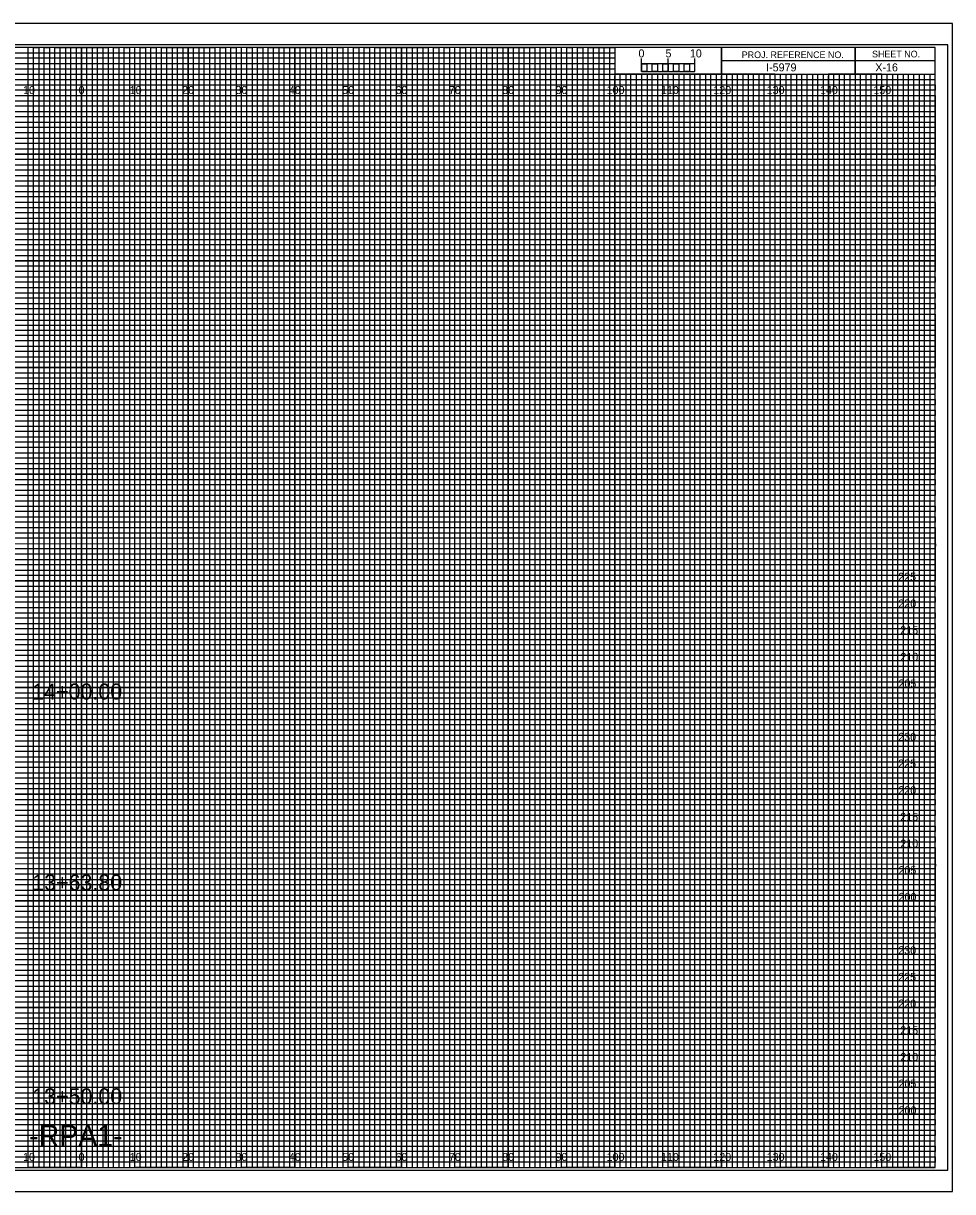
# Model space of a CAD drawing. Extents: x -13 to 323, y -5 to 654.
# Drawn here: x 149.1 to 323.3, y 435.5 to 654.5 of the extents above; entities that cross this region are included whole.
import ezdxf

# ---------------------------------------------------------------- set-up
doc = ezdxf.new("R2010")
doc.units = 0
for name, color, linetype in [('Prop XS Alignment Label', 7, 'Continuous'), ('Prop XS Bar Scale Labels', 7, 'Continuous'), ('Prop XS Elevation Labels', 7, 'Continuous'), ('Prop XS Offset Labels', 7, 'Continuous'), ('Prop XS Project Number', 7, 'Continuous'), ('Prop XS Sheet Number', 7, 'Continuous'), ('Prop XS Station Labels', 7, 'Continuous'), ('Sheet Cross Section CELL', 7, 'Continuous'), ('Sheet Cross Section Grid Major CELL', 7, 'Continuous'), ('Sheet Cross Section Grid Middle CELL', 7, 'Continuous'), ('Sheet Cross Section Grid Minor 1 CELL', 7, 'Continuous'), ('Sheet Cross Section Grid Minor 2 CELL', 7, 'Continuous'), ('Sheet Cross Section Scale CELL', 7, 'Continuous'), ('Sheet Cutting Line CELL', 7, 'Continuous'), ('Sheet DOT Grid CELL', 7, 'Continuous'), ('Sheet Plot Border Inside CELL', 7, 'Continuous'), ('Sheet Plot Border Outside CELL', 7, 'Continuous')]:
    doc.layers.add(name, color=color, linetype=linetype)

msp = doc.modelspace()

# ---------------------------------------------------------------- linework, layer by layer
at = {"layer": 'Sheet Cross Section CELL'}
for p, q in [((305, 650), (305, 645)), ((305, 645), (305, 650)), ((280, 647.5), (280, 645)), ((320, 647.49), (280, 647.49)), ((280, 645), (320, 645))]:
    msp.add_line(p, q, dxfattribs=at)
for points in [[(320, 650), (0, 650), (0, 440), (320, 440)], [(280, 650), (260, 650), (260, 645.03), (280, 645.03)], [(320, 650), (280, 650), (280, 645), (320, 645)]]:
    msp.add_lwpolyline(points, close=True, dxfattribs=at)
at = {"layer": 'Sheet Cross Section Grid Major CELL'}
for p, q in [((150, 650), (140, 650)), ((150, 440), (150, 650)), ((170, 650), (160, 650)), ((160, 650), (160, 440)), ((170, 440), (170, 650)), ((190, 650), (180, 650)), ((180, 650), (180, 440)), ((190, 440), (190, 650)), ((210, 650), (200, 650)), ((200, 650), (200, 440)), ((210, 440), (210, 650)), ((230, 650), (220, 650)), ((220, 650), (220, 440)), ((230, 440), (230, 650)), ((250, 650), (240, 650)), ((240, 650), (240, 440)), ((250, 440), (250, 650)), ((260, 650), (260, 440)), ((270, 440), (270, 645)), ((290, 645), (280, 645)), ((280, 645), (280, 440)), ((290, 440), (290, 645)), ((310, 645), (300, 645)), ((300, 645), (300, 440)), ((310, 440), (310, 645)), ((160, 440), (150, 440)), ((180, 440), (170, 440)), ((200, 440), (190, 440)), ((220, 440), (210, 440)), ((240, 440), (230, 440)), ((260, 440), (250, 440)), ((280, 440), (270, 440)), ((300, 440), (290, 440)), ((320, 440), (310, 440)), ((320, 440), (320, 440))]:
    msp.add_line(p, q, dxfattribs=at)
for points in [[(0, 640), (320, 640), (320, 630), (0, 630)], [(0, 620), (320, 620), (320, 610), (0, 610)], [(0, 600), (320, 600), (320, 590), (0, 590)], [(0, 580), (320, 580), (320, 570), (0, 570)], [(0, 560), (320, 560), (320, 550), (0, 550)], [(0, 540), (320, 540), (320, 530), (0, 530)], [(0, 520), (320, 520), (320, 510), (0, 510)], [(0, 500), (320, 500), (320, 490), (0, 490)], [(0, 480), (320, 480), (320, 470), (0, 470)], [(0, 460), (320, 460), (320, 450), (0, 450)]]:
    msp.add_lwpolyline(points, dxfattribs=at)
at = {"layer": 'Sheet Cross Section Grid Middle CELL'}
for points in [[(145, 440), (155, 440), (155, 650), (165, 650), (165, 440), (175, 440), (175, 650), (185, 650), (185, 440), (195, 440), (195, 650), (205, 650), (205, 440), (215, 440), (215, 650), (225, 650), (225, 440), (235, 440), (235, 650), (245, 650), (245, 440), (255, 440), (255, 650), (259.93, 650), (260, 650), (260, 645), (264.99, 645), (264.99, 440), (275, 440), (275, 645), (285, 645), (285, 440), (295, 440), (295, 645), (305, 645), (305, 440), (315, 440), (315, 645)], [(0, 645), (275, 645)], [(0, 625), (320, 625), (320, 635), (0, 635)], [(0, 605), (320, 605), (320, 615), (0, 615)], [(0, 585), (320, 585), (320, 595), (0, 595)], [(0, 565), (320, 565), (320, 575), (0, 575)], [(0, 545), (320, 545), (320, 555), (0, 555)], [(0, 525), (320, 525), (320, 535), (0, 535)], [(0, 505), (320, 505), (320, 515), (0, 515)], [(0, 485), (320, 485), (320, 495), (0, 495)], [(0, 465), (320, 465), (320, 475), (0, 475)], [(0, 445), (320, 445), (320, 455), (0, 455)]]:
    msp.add_lwpolyline(points, dxfattribs=at)
at = {"layer": 'Sheet Cross Section Grid Minor 1 CELL'}
for p, q in [((0, 649), (260, 649)), ((260, 649), (260, 647.98)), ((260, 647.98), (0, 647.98)), ((0, 647), (260, 647)), ((260, 647), (260, 645.89)), ((260, 645.89), (0, 645.89)), ((0, 644), (320, 644))]:
    msp.add_line(p, q, dxfattribs=at)
for points in [[(0, 643), (270, 643), (320, 643), (320, 642), (0, 642)], [(0, 641), (320, 641), (320, 639), (0, 639)], [(0, 638), (320, 638), (320, 637), (0, 636.98)], [(0, 636), (320, 636), (320, 634), (0, 634)], [(0, 633), (320, 633), (320, 632), (0, 632)], [(0, 631), (320, 631), (320, 629), (0, 629)], [(0, 628), (320, 628), (320, 627), (0, 627)], [(0, 626), (320, 626), (320, 624), (0, 624)], [(0, 623), (320, 623), (320, 622), (0, 622)], [(0, 621), (320, 621), (320, 619), (0, 619)], [(0, 618), (320, 618), (320, 617), (0, 617)], [(0, 616), (320, 616), (320, 613.95), (320, 613), (320, 612), (0, 612)], [(0, 614), (320, 614), (320, 613), (0, 613)], [(0, 611), (320, 611), (320, 609), (0, 609.03)], [(0, 609.03), (320, 609), (320, 608), (0, 608)], [(0, 607), (320, 607), (320, 606), (0, 606)], [(0, 604), (320, 604), (320, 603), (0, 603)], [(0, 602), (320, 602), (320, 601), (0, 601)], [(-0.07, 598.89), (320, 598.89), (320, 597.88), (-0.07, 597.88)], [(0, 597), (320, 597), (320, 596), (0, 596)], [(0, 594), (320, 594), (320, 593), (0, 593)], [(0, 592), (320, 592), (320, 591), (0, 591)], [(0, 589), (320, 589), (320, 588), (0, 588)], [(0, 587), (320, 587), (320, 586), (0, 586)], [(0, 584), (320, 584), (320, 583), (0, 583)], [(0, 582), (320, 582), (320, 581), (0, 581)], [(0, 579), (320, 579), (319.99, 577.98), (0, 578)], [(0, 577), (320, 577), (320, 576), (0, 576)], [(0, 574), (320, 574), (320, 573), (0, 573)], [(0, 572), (320, 572), (320, 571), (0, 571)], [(0, 569), (320, 569), (320, 568), (0, 568)], [(0, 567), (320, 567), (320, 566), (0, 566)], [(0, 564), (320, 564), (320, 563), (0, 563)], [(0, 562), (320, 562), (320, 561), (0, 561)], [(0, 559), (320, 559), (320, 558), (0, 558)], [(0, 556.99), (320.07, 556.91), (320, 556), (0, 556)], [(0, 554), (320, 554), (320, 553), (0, 553)], [(0, 552), (320, 552), (320, 551), (0, 551)], [(0, 549), (320, 549), (320, 548), (0, 548)], [(0, 547), (320, 547), (320, 546), (0, 546)], [(0, 544), (320, 544), (320, 543), (0, 543)], [(0, 542), (320, 542), (320, 541), (0, 541)], [(0, 539), (320, 539), (320, 538), (0, 538)], [(0, 537), (320, 537), (320, 536), (0, 536)], [(0, 534), (320, 534), (320, 533), (0, 533)], [(0, 532), (320, 532), (320, 531), (0, 531)], [(0, 529), (320, 529), (320, 528), (0, 528)], [(0, 527), (320, 527), (320, 526), (0, 526)], [(0, 524), (320, 524), (320, 523), (0, 523)], [(0, 522), (320, 522), (320, 521), (0, 521)], [(0, 519), (320, 519), (319.99, 517.98), (0, 518)], [(0, 517), (320, 517), (320, 516), (0, 516)], [(0, 514), (320, 514), (320, 513), (0, 513)], [(0, 512), (320, 512), (320, 511), (0, 511)], [(0, 509), (320, 509), (320, 508), (0, 508)], [(0, 507), (320, 507), (320, 506), (0, 506)], [(0, 504), (320, 504), (320, 503), (0, 503)], [(0, 502), (320, 502), (320, 501), (0, 501)], [(0, 499), (320, 499), (320, 498), (0, 498)], [(0, 496.99), (320.07, 496.91), (320, 496), (0, 496)], [(0, 494), (320, 494), (320, 493), (0, 493)], [(0, 492), (320, 492), (320, 491), (0, 491)], [(0, 489), (320, 489), (320, 488), (0, 488)], [(0, 487), (320, 487), (320, 486), (0, 486)], [(0, 484), (320, 484), (320, 483), (0, 483)], [(0, 482), (320, 482), (320, 481), (0, 481)], [(0, 479), (320, 479), (320, 478), (0, 478)], [(0, 477), (320, 477), (320, 476), (0, 476)], [(0, 474), (320, 474), (320, 473), (0, 473)], [(0, 472), (320, 472), (320, 471), (0, 471)], [(0, 469), (320, 469), (320, 468), (0, 468)], [(0, 467), (320, 467), (320, 466), (0, 466)], [(0, 464), (320, 464), (320, 463), (0, 463)], [(0, 462), (320, 462), (320, 461), (0, 461)], [(0, 459), (320, 459), (320, 458), (0, 458)], [(0, 457), (320, 457), (320, 456), (0, 456)], [(0, 454), (320, 454), (320, 453), (0, 453)], [(0, 452), (320, 452), (320, 451), (0, 451)], [(0, 449), (320, 449), (320, 448), (0, 448)], [(0, 447), (320, 447), (320, 446), (0, 446)], [(0, 444), (320, 444), (320, 443), (0, 443)], [(0, 442), (320, 442), (320, 441), (0, 441)]]:
    msp.add_lwpolyline(points, dxfattribs=at)
at = {"layer": 'Sheet Cross Section Grid Minor 2 CELL'}
for p, q in [((267, 645), (266.01, 645)), ((266.01, 645), (266.01, 440)), ((267, 440), (267, 645)), ((269, 645), (268, 645)), ((268, 645), (268, 440)), ((269, 440), (269, 645)), ((266.01, 440), (265, 440)), ((268, 440), (267, 440))]:
    msp.add_line(p, q, dxfattribs=at)
for points in [[(150, 440), (151, 440), (151, 650), (152, 650), (152, 440)], [(152, 440), (153, 440), (153, 650), (154, 650), (154, 440)], [(155, 440), (156, 440), (156, 650), (157, 650), (157, 440)], [(157, 440), (158, 440), (158, 650), (159, 650), (159, 440)], [(160, 440), (161, 440), (161, 650), (162, 650), (162, 440)], [(162, 440), (163, 440), (163, 650), (164, 650), (164, 440)], [(165, 440), (166, 440), (166, 650), (167, 650), (167, 440)], [(167, 440), (168, 440), (168, 650), (169, 650), (169, 440)], [(170, 440), (171, 440), (171, 650), (172, 650), (172, 440)], [(172, 440), (173, 440), (173, 650), (174, 650), (174, 440)], [(175, 440), (176, 440), (176, 650), (177, 650), (177, 440)], [(177, 440), (178, 440), (178, 650), (179, 650), (179, 440)], [(180, 440), (181, 440), (181, 650), (182, 650), (182, 440)], [(182, 440), (183, 440), (183, 650), (184, 650), (184, 440)], [(185, 440), (186, 440), (186, 650), (187, 650), (187, 440)], [(187, 440), (188, 440), (188, 650), (189, 650), (189, 440)], [(190, 440), (191, 440), (191, 650), (192, 650), (192, 440)], [(192, 440), (193, 440), (193, 650), (194, 650), (194, 440)], [(195, 440), (196, 440), (196, 650), (197, 650), (197, 440)], [(197, 440), (198, 440), (198, 650), (199, 650), (199, 440)], [(200, 440), (201, 440), (201, 650), (202, 650), (202, 440)], [(202, 440), (203, 440), (203, 650), (204, 650), (204, 440)], [(205, 440), (206, 440), (206, 650), (207, 650), (207, 440)], [(207, 440), (208, 440), (208, 650), (209, 650), (209, 440)], [(210, 440), (211, 440), (211, 650), (212, 650), (212, 440)], [(212, 440), (213, 440), (213, 650), (214, 650), (214, 440)], [(215, 440), (216, 440), (216, 650), (217, 650), (217, 440)], [(217, 440), (218, 440), (218, 650), (219, 650), (219, 440)], [(220, 440), (221, 440), (221, 650), (222, 650), (222, 440)], [(222, 440), (223, 440), (223, 650), (224, 650), (224, 440)], [(225, 440), (226, 440), (226, 650), (227, 650), (227, 440)], [(227, 440), (228, 440), (228, 650), (229, 650), (229, 440)], [(230, 440), (231, 440), (231, 650), (232, 650), (232, 440)], [(232, 440), (233, 440), (233, 650), (234, 650), (234, 440)], [(235, 440), (236, 440), (236, 650), (237, 650), (237, 440)], [(237, 440), (238, 440), (238, 650), (239, 650), (239, 440)], [(240, 440), (241, 440), (241, 650), (242, 650), (242, 440)], [(242, 440), (243, 440), (243, 650), (244, 650), (244, 440)], [(245, 440), (246, 440), (246, 650), (247, 650), (247, 440)], [(247, 440), (248, 440), (248, 650), (249, 650), (249, 440)], [(250, 440), (251, 440), (251, 650), (252, 650), (252, 440)], [(252, 440), (253, 440), (253, 650), (254, 650), (254, 440)], [(255, 440), (256, 440), (256, 650), (257, 650), (257, 440)], [(257, 440), (258, 440), (258, 650), (259, 650), (259, 440)], [(260, 440), (261, 440), (261, 645), (262.02, 645), (262.02, 440)], [(262, 440), (263, 440), (263, 645), (263.99, 645), (263.99, 440)], [(270, 440), (270.98, 440), (270.98, 645), (272, 645), (272, 440)], [(272, 440), (273, 440), (273, 645), (274.05, 645), (274.05, 440)], [(275, 440), (276, 440), (276, 645), (277, 645), (277, 440)], [(277, 440), (278, 440), (278, 645), (279, 645), (279, 440)], [(280, 440), (281, 440), (281, 645), (282, 645), (282, 440)], [(282, 440), (283, 440), (283, 645), (284, 645), (284, 440)], [(285, 440), (286, 440), (286, 645), (287, 645), (287, 440)], [(287, 440), (288, 440), (288, 645), (289, 645), (289, 440)], [(290, 440), (291, 440), (291, 645), (292, 645), (292, 440)], [(292, 440), (293, 440), (293, 645), (294, 645), (294, 440)], [(295, 440), (296, 440), (296, 645), (297, 645), (297, 440)], [(297, 440), (298, 440), (298, 645), (299, 645), (299, 440)], [(300, 440), (301, 440), (301, 645), (302, 645), (302, 440)], [(302, 440), (303, 440), (303, 645), (304, 645), (304, 440)], [(305, 440), (306, 440), (306, 645), (307, 645), (307, 440)], [(307, 440), (308, 440), (308, 645), (309, 645), (309, 440)], [(310, 440), (311, 440), (311, 645), (312, 645), (312, 440)], [(312, 440), (313, 440), (313, 645), (314, 645), (314, 440)], [(315, 440), (316, 440), (316, 645), (317, 645), (317, 440)], [(317, 440), (318, 440), (318, 645), (319, 645), (319, 440)]]:
    msp.add_lwpolyline(points, dxfattribs=at)
at = {"layer": 'Sheet Cross Section Scale CELL'}
for p, q in [((265, 645.49), (265, 647.9)), ((265, 646.9), (265, 647.9)), ((270, 645.49), (270, 647.9)), ((275, 645.49), (275, 647.9)), ((275, 646.9), (275, 647.9))]:
    msp.add_line(p, q, dxfattribs=at)
for points in [[(275, 646.9), (265, 646.9), (265, 645.49), (275, 645.49)], [(265, 646.9), (266, 646.9), (266, 645.49), (265, 645.49)], [(267, 646.9), (268, 646.9), (268, 645.49), (267, 645.49)], [(269, 646.9), (270, 646.9), (270, 645.49), (269, 645.49)], [(271, 646.9), (272, 646.9), (272, 645.49), (271, 645.49)], [(273, 646.9), (274, 646.9), (274, 645.49), (273, 645.49)]]:
    msp.add_lwpolyline(points, close=True, dxfattribs=at)
at = {"layer": 'Sheet Cutting Line CELL'}
for p, q in [((323.3, 654.5), (-13.4, 654.5)), ((-13.4, 435.5), (323.3, 435.5))]:
    msp.add_line(p, q, dxfattribs=at)
at = {"layer": 'Sheet DOT Grid CELL'}
for p, q in [((150, 440), (150, 650)), ((160, 440), (160, 650)), ((170, 440), (170, 650)), ((180, 440), (180, 650)), ((190, 440), (190, 650)), ((200, 440), (200, 650)), ((210, 440), (210, 650)), ((220, 440), (220, 650)), ((230, 440), (230, 650)), ((240, 440), (240, 650)), ((250, 440), (250, 650)), ((260, 440), (260, 644.69)), ((270, 440), (270, 644.69)), ((280, 440), (280, 644.69)), ((290, 440), (290, 644.69)), ((300, 440), (300, 644.69)), ((310, 440), (310, 644.69)), ((0, 640), (320, 640)), ((0, 630), (320, 630)), ((0, 620), (320, 620)), ((0, 610), (320, 610)), ((0, 600), (320, 600)), ((0, 590), (320, 590)), ((0, 580), (320, 580)), ((0, 570), (320, 570)), ((0, 560), (320, 560)), ((0, 550), (320, 550)), ((0, 540), (320, 540)), ((0, 530), (320, 530)), ((0, 520), (320, 520)), ((0, 510), (320, 510)), ((0, 500), (320, 500)), ((0, 490), (320, 490)), ((0, 480), (320, 480)), ((0, 470), (320, 470)), ((0, 460), (320, 460)), ((0, 450), (320, 450))]:
    msp.add_line(p, q, dxfattribs=at)
at = {"layer": 'Sheet Plot Border Inside CELL'}
msp.add_lwpolyline([(-10.8, 439.5), (322.4, 439.5), (322.4, 650.5), (-10.8, 650.5)], close=True, dxfattribs=at)
at = {"layer": 'Sheet Plot Border Outside CELL'}
msp.add_lwpolyline([(-13.4, 435.5), (323.3, 435.5), (323.3, 654.5), (-13.4, 654.5)], close=True, dxfattribs=at)

# ---------------------------------------------------------------- texts
at = {"layer": 'Prop XS Alignment Label'}
msp.add_text('-RPA1-', height=4, dxfattribs=at).set_placement((150.18, 444))
at = {"layer": 'Prop XS Bar Scale Labels'}
for s, p in [('5', (269.47, 648.12)), ('10', (274.04, 648.12))]:
    msp.add_text(s, height=1.5, dxfattribs=at).set_placement(p)
at = {"layer": 'Prop XS Elevation Labels'}
for s, p in [('225', (313.1, 550)), ('220', (313.12, 545)), ('215', (313.48, 540)), ('210', (313.5, 535)), ('205', (313.15, 530)), ('230', (313.11, 520)), ('225', (313.1, 515)), ('220', (313.12, 510)), ('215', (313.48, 505)), ('210', (313.5, 500)), ('205', (313.15, 495)), ('200', (313.17, 490)), ('230', (313.11, 480)), ('225', (313.1, 475)), ('220', (313.12, 470)), ('215', (313.48, 465)), ('210', (313.5, 460)), ('205', (313.15, 455)), ('200', (313.17, 450))]:
    msp.add_text(s, height=1.5, dxfattribs=at).set_placement(p)
at = {"layer": 'Prop XS Offset Labels'}
for s, p in [('10', (149.04, 641.25)), ('0', (159.45, 641.25)), ('0', (159.45, 641.25)), ('10', (169.04, 641.25)), ('20', (178.86, 641.25)), ('30', (188.86, 641.25)), ('40', (198.86, 641.25)), ('50', (208.86, 641.25)), ('60', (218.86, 641.25)), ('70', (228.86, 641.25)), ('80', (238.86, 641.25)), ('90', (248.86, 641.25)), ('100', (258.44, 641.25)), ('110', (268.62, 641.25)), ('120', (278.44, 641.25)), ('130', (288.44, 641.25)), ('140', (298.44, 641.25)), ('150', (308.44, 641.25)), ('10', (149.04, 441.25)), ('0', (159.45, 441.25)), ('0', (159.45, 441.25)), ('10', (169.04, 441.25)), ('20', (178.86, 441.25)), ('30', (188.86, 441.25)), ('40', (198.86, 441.25)), ('50', (208.86, 441.25)), ('60', (218.86, 441.25)), ('70', (228.86, 441.25)), ('80', (238.86, 441.25)), ('90', (248.86, 441.25)), ('100', (258.44, 441.25)), ('110', (268.62, 441.25)), ('120', (278.44, 441.25)), ('130', (288.44, 441.25)), ('140', (298.44, 441.25)), ('150', (308.44, 441.25))]:
    msp.add_text(s, height=1.5, dxfattribs=at).set_placement(p)
at = {"layer": 'Prop XS Project Number'}
msp.add_text('I-5979', height=1.5, dxfattribs=at).set_placement((288.34, 645.5))
at = {"layer": 'Prop XS Sheet Number'}
msp.add_text('X-16', height=1.5, dxfattribs=at).set_placement((308.8, 645.5))
at = {"layer": 'Prop XS Station Labels'}
for s, p in [('14+00.00', (150.77, 527.75)), ('13+63.80', (150.77, 491.96)), ('13+50.00', (150.77, 451.87))]:
    msp.add_text(s, height=3, dxfattribs=at).set_placement(p)
at = {"layer": 'Sheet Cross Section CELL'}
for s, p in [('PROJ. REFERENCE NO.', (283.77, 647.99)), ('SHEET NO.', (308.19, 648.12))]:
    msp.add_text(s, height=1.25, dxfattribs=at).set_placement(p)
at = {"layer": 'Sheet Cross Section Scale CELL'}
msp.add_text('0', height=1.5, dxfattribs=at).set_placement((264.41, 648.12))

doc.saveas('drawing.dxf')
